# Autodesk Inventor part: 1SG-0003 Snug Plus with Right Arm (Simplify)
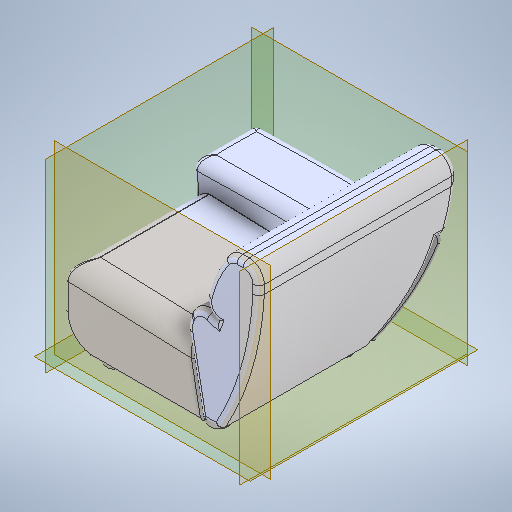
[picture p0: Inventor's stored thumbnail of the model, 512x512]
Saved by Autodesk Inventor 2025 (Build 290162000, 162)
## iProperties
Created: 2025-08
Part Number: 1SG-0003 Snug Plus with Right Arm (Simplify)
Material: Generic
Document SubType Name: Modeling
Designer: Mark.Glazzard
Density: 1 g/cm^3
Appearance: Default
Author: Mark.Glazzard
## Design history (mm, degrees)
derived "1SG-0003 Snug Plus with Ri.iam"
workplane "Work Plane1"
workplane "Work Plane2"
workplane "Work Plane3"
workplane "Work Plane4"
workplane "Work Plane5"
body "Solid1"
node "1SG-0003 Back Subassembly_.iam:1::BACK UPHOLSTERED.ipt:1"
node "1SG-0003 Arm Subassembly_U.iam:1::ARM UPHOLSTERED.ipt:1"
node "1SG-0003 Seat Subassembly_.iam:1::SEAT UPHOLSTERED^1SG-0003 "
node "PCM5592 - Snug Feet (Rev E.ipt:1"
node "PCM5592 - Snug Feet (Rev E.ipt:2"
node "PCM5592 - Snug Feet (Rev E.ipt:3"
node "PCM5592 - Snug Feet (Rev E.ipt:4"
node "1SG-0003 Snug Plus with Ri.iam_Bodies"
